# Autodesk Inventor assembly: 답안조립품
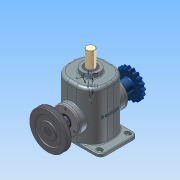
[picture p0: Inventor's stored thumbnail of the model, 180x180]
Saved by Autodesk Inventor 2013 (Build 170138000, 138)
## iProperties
Created: 2014-12
Part Number: 답안조립품
Document SubType Name: Assembly
Designer: Administrator
Author: Administrator
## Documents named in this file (15)
- C:\Users\Administrator\Desktop\341209V1023\341209V1023\답안조립품.iam
- C:\Users\Administrator\Desktop\341209V1023\341209V1023\본체.ipt
- C:\Users\Administrator\Desktop\341209V1023\341209V1023\편심축.ipt
- C:\Users\Administrator\Desktop\341209V1023\341209V1023\V-벨트풀리.ipt
- C:\Users\Administrator\Desktop\341209V1023\341209V1023\체인 스프로킷.ipt
- C:\Users\Administrator\Desktop\341209V1023\341209V1023\커버.ipt
- C:\Users\Administrator\Desktop\341209V1023\341209V1023\슬라이드.ipt
- C:\Users\Administrator\Desktop\341209V1023\341209V1023\가변스프링.ipt
- C:\Users\Administrator\Desktop\341209V1023\341209V1023\베어링 6205.ipt
- C:\Users\Administrator\Desktop\341209V1023\341209V1023\오일실.ipt
- C:\Users\Administrator\Desktop\341209V1023\341209V1023\부시.ipt
- C:\Users\Administrator\Desktop\341209V1023\341209V1023\키 8x8.ipt
- C:\Users\Administrator\Desktop\341209V1023\341209V1023\멈춤링.ipt
- C:\Users\Administrator\Desktop\341209V1023\341209V1023\M4x0.5.ipt
- C:\Users\Administrator\Desktop\341209V1023\341209V1023\멈춤나사 M5x0.5.ipt
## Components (9 placed, 4 different names)
1. V-벨트풀리:1
2. 5-체인 스프로킷:1
3. 가변스프링:1
4. M4x0.5:1
5. M4x0.5:2
6. M4x0.5:3
7. M4x0.5:4
8. M4x0.5:5
9. M4x0.5:6
